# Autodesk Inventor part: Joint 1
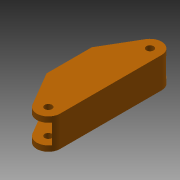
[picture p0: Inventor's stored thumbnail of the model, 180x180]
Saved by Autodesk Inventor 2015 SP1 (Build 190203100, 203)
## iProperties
Created: 2008-11
Part Number: Joint 1
Document SubType Name: Modeling
Designer: dwoollam
Density: 7.85 g/cm^3
Material: Steel
Appearance: Orange
Mass: 284274 g
Surface Area: 16014.6 cm^2
Volume: 36213.2 cm^3
Dwg_Category: Clearance_Mewp
INSTALLATION: False
CIVIL_WORK: False
EARTHING: False
MOUNTING: False
Author: dwoollam
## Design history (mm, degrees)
sketch "Sketch1"
  geometry: L1 (0, -415)-(0, 415); L2 (-245, 185)-(-245, -185); L3 (95, 415)-(95, -415); L4 (-81.95, 463.055)-(-245, 185); L5 (-81.95, -463.055)-(-245, -185); L6 (80, 90)-(-270, 90); L7 (-270, 90)-(-270, 540); L8 (-270, 540)-(80, 540); L9 (80, 540)-(80, 90); L10 (80, -90)-(-270, -90); L11 (-270, -90)-(-270, -540); L12 (-270, -540)-(80, -540); L13 (80, -540)-(80, -90); C1 r 30 at (0, 415); C2 r 30 at (0, -415); A1 r 95 centre (0, 415) between (95, 415) and (-81.95, 463.055); A2 r 95 centre (0, -415) between (-81.95, -463.055) and (95, -415); 3 further points
  constraints: 26 end point, 5 parallel, 4 centre point, 4 coincident, 4 point on circle, 4 tangent, 2 equal length, 2 equal radius, 2 horizontal, 2 midpoint, 2 perpendicular, 1 horizontal alignment, 1 vertical
  dimensions: "d0" = 190 diameter of A2; "d1" = 60 diameter of C2; "d2" = 830 distance of L1.start L1.end; "d3" = 370 distance of L2.start L2.end; "d4" = 340 distance between parallel lines of L3 L2; "d5" = 325 distance from line of A2.centre L10; "d6" = 325 distance from line of A1.centre L6 (= d5); "d7" = 80 distance from line of L9 A1.centre; "d8" = 80 distance from line of A2.centre L13 (= d7); "d9" = 350 distance of L11.end L12.end; "d10" = 450 distance of L10.end L11.end
extrude "Part_1" new body sketch "Sketch1" stored distance "d11" = 250; taper "d12" = 0 deg
extrude "Part_1_Sub" cut sketch "Sketch1" stored distance "d13" = 160; taper "d14" = 0 deg
body "Solid1"
